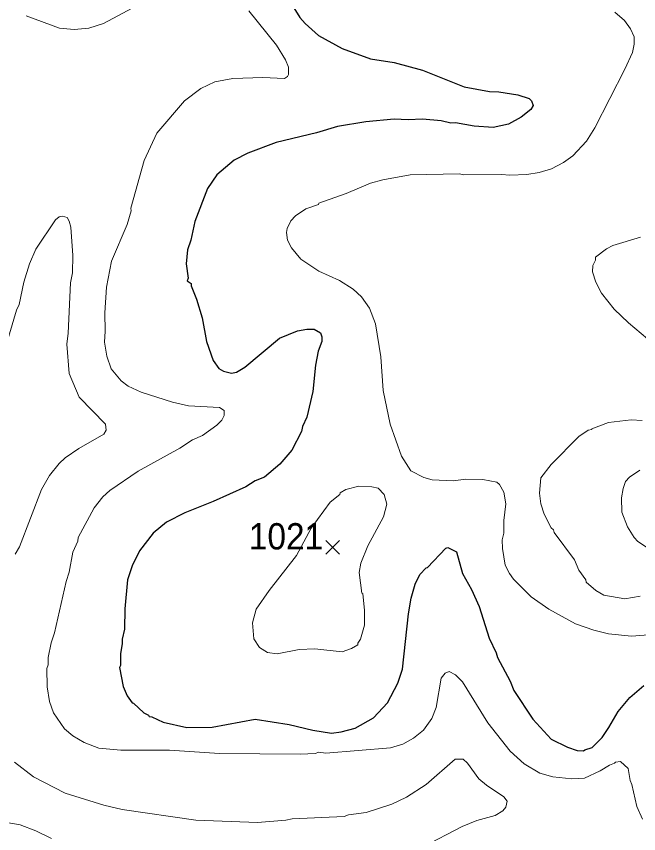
# Model space of a CAD drawing. Extents: x 265.7 to 292.1, y 7676.2 to 7704.2.
# Drawn here: x 284.034 to 285.928, y 7695.33 to 7697.815 of the extents above; entities that cross this region are included whole.
import ezdxf
from ezdxf.enums import TextEntityAlignment as Align

# ---------------------------------------------------------------- set-up
doc = ezdxf.new("R2010")
doc.units = 0
doc.header["$LTSCALE"] = 0.032
for name, color, linetype, lineweight in [('1', 7, 'Continuous', 25), ('2', 7, 'Continuous', 13), ('21', 7, 'Continuous', 25)]:
    doc.layers.add(name, color=color, linetype=linetype, lineweight=lineweight)
doc.layers.add('61', color=7, linetype='Continuous')

msp = doc.modelspace()

# ---------------------------------------------------------------- linework, layer by layer
at = {"layer": '1'}
for points in [[(284.8787, 7697.8409), (284.8971, 7697.8114), (284.913, 7697.7931), (284.9537, 7697.7563), (285.0256, 7697.7172), (285.1117, 7697.6861), (285.1836, 7697.675), (285.2697, 7697.651), (285.3974, 7697.6007), (285.474, 7697.5864), (285.5027, 7697.5856), (285.5602, 7697.5768), (285.5945, 7697.5656), (285.6017, 7697.5577), (285.6073, 7697.5441), (285.6001, 7697.5321), (285.5705, 7697.5082), (285.5315, 7697.4874), (285.4852, 7697.4771), (285.4277, 7697.4811), (285.3703, 7697.4914), (285.3559, 7697.4906), (285.3272, 7697.497), (285.2697, 7697.5026), (285.2266, 7697.5002), (285.1836, 7697.5026), (285.0974, 7697.4946), (285.0112, 7697.4803), (284.9474, 7697.4603), (284.8245, 7697.4316), (284.7383, 7697.3989), (284.6968, 7697.3773), (284.6441, 7697.3334), (284.6162, 7697.2919), (284.5779, 7697.1914), (284.5651, 7697.134), (284.5555, 7697.1052), (284.5516, 7697.0621), (284.5571, 7697.019), (284.5547, 7697.0103), (284.5659, 7697.0023), (284.5659, 7696.9951), (284.5827, 7696.9552), (284.5994, 7696.8978), (284.613, 7696.8259), (284.6329, 7696.7685), (284.6505, 7696.7437), (284.6649, 7696.7365), (284.6888, 7696.7302), (284.7048, 7696.7334), (284.7295, 7696.7485), (284.8348, 7696.8363), (284.8899, 7696.8586), (284.9186, 7696.8642), (284.9402, 7696.8642), (284.9601, 7696.8523), (284.9641, 7696.8403), (284.9641, 7696.8259), (284.9529, 7696.7972), (284.9442, 7696.7541), (284.937, 7696.6743), (284.9178, 7696.5961), (284.905, 7696.5674), (284.9019, 7696.553), (284.8723, 7696.4956), (284.8364, 7696.4533), (284.7894, 7696.4142), (284.7606, 7696.4022), (284.7327, 7696.3847), (284.633, 7696.34), (284.5468, 7696.3057), (284.4917, 7696.2769)], [(284.4917, 7696.2769), (284.451, 7696.2434), (284.4095, 7696.19), (284.3864, 7696.1445), (284.3728, 7696.1014), (284.3648, 7696.0136), (284.3632, 7695.9514)], [(284.3632, 7695.9514), (284.3561, 7695.921), (284.3569, 7695.9067), (284.3513, 7695.878), (284.3513, 7695.8412), (284.3481, 7695.8349), (284.3592, 7695.7774), (284.372, 7695.7487), (284.3864, 7695.7271), (284.3912, 7695.7263), (284.4223, 7695.6976), (284.4367, 7695.6904), (284.4391, 7695.6856), (284.447, 7695.6848), (284.4813, 7695.6689), (284.5532, 7695.6521), (284.6298, 7695.6537), (284.7606, 7695.6777), (284.8644, 7695.6617), (284.9362, 7695.6441), (284.9936, 7695.6354), (285.0224, 7695.6394), (285.0655, 7695.6505), (285.1213, 7695.6824), (285.1636, 7695.7279), (285.1955, 7695.787), (285.2091, 7695.8301), (285.2274, 7695.9977), (285.2362, 7696.0455), (285.2482, 7696.0886), (285.2625, 7696.1173), (285.2809, 7696.1381), (285.2857, 7696.1389), (285.3415, 7696.1979), (285.3471, 7696.2003), (285.3735, 7696.1868), (285.3918, 7696.1205), (285.4197, 7696.0719), (285.4429, 7696.02), (285.4732, 7695.9242), (285.4947, 7695.8796), (285.4987, 7695.8652), (285.537, 7695.7934), (285.5482, 7695.7646), (285.6057, 7695.6777), (285.6615, 7695.617), (285.7118, 7695.5923), (285.7405, 7695.5827), (285.7605, 7695.5811), (285.7637, 7695.5851), (285.7868, 7695.5915), (285.8163, 7695.6226), (285.8371, 7695.6521), (285.865, 7695.7008), (285.9009, 7695.7439), (285.944, 7695.7806)]]:
    msp.add_lwpolyline(points, dxfattribs=at)
at = {"layer": '2'}
for points in [[(284.3872, 7697.8401), (284.2994, 7697.7931), (284.2547, 7697.7795), (284.21, 7697.7755), (284.1654, 7697.7795), (284.0648, 7697.8162)], [(284.8628, 7697.6383), (284.8628, 7697.6606), (284.8532, 7697.6829), (284.8261, 7697.7276), (284.7415, 7697.8322)], [(285.0846, 7696.9616), (285.0591, 7696.9855), (285.0176, 7697.0119), (284.9553, 7697.0406), (284.9003, 7697.0765), (284.8715, 7697.1116), (284.8596, 7697.134), (284.8564, 7697.1579), (284.858, 7697.1699), (284.8699, 7697.193), (284.8843, 7697.2082), (284.9154, 7697.2297), (284.9537, 7697.2425), (284.9545, 7697.2465), (285.0383, 7697.2768), (285.1117, 7697.3079), (285.15, 7697.3183), (285.233, 7697.3326), (285.383, 7697.3358), (285.3958, 7697.3326), (285.5107, 7697.3342), (285.5363, 7697.3318), (285.5873, 7697.3342), (285.6256, 7697.3406), (285.6623, 7697.3518), (285.699, 7697.3701), (285.7278, 7697.3909), (285.7693, 7697.4356), (285.7948, 7697.4755), (285.8858, 7697.6542), (285.9089, 7697.7053), (285.9145, 7697.7308), (285.9137, 7697.7532), (285.9033, 7697.7771), (285.885, 7697.8026), (285.8554, 7697.8274)], [(284.5962, 7697.5952), (284.6385, 7697.6159), (284.6936, 7697.6263), (284.7846, 7697.6287), (284.85, 7697.6263), (284.8596, 7697.6319), (284.8628, 7697.6383)], [(285.94, 7695.3736), (285.9225, 7695.412), (285.9073, 7695.479), (285.9017, 7695.4909), (285.8961, 7695.5277), (285.873, 7695.5492), (285.857, 7695.5476), (285.8546, 7695.5436), (285.8395, 7695.538), (285.8108, 7695.5205), (285.7629, 7695.4989), (285.7246, 7695.4965), (285.6671, 7695.5029), (285.6272, 7695.5141), (285.5793, 7695.542), (285.537, 7695.5803), (285.4692, 7695.6665), (285.3918, 7695.7918), (285.3703, 7695.8125), (285.3511, 7695.8229), (285.3391, 7695.8173), (285.3272, 7695.8022), (285.312, 7695.7136), (285.2985, 7695.6801), (285.2729, 7695.6441), (285.2426, 7695.6202), (285.2107, 7695.6019), (285.1724, 7695.5907), (284.9761, 7695.5747), (284.9537, 7695.5779), (284.945, 7695.5739), (284.8979, 7695.5715), (284.6521, 7695.5739), (284.5005, 7695.5835), (284.3521, 7695.5835), (284.285, 7695.5899), (284.2404, 7695.6066), (284.206, 7695.6274), (284.1813, 7695.6481), (284.1478, 7695.6976), (284.135, 7695.7311), (284.1286, 7695.7758), (284.127, 7695.8317), (284.1318, 7695.8428), (284.1318, 7695.8652), (284.1406, 7695.9099), (284.151, 7695.9402), (284.1861, 7696.0966), (284.1957, 7696.1253), (284.2068, 7696.186), (284.2212, 7696.2195), (284.2228, 7696.2307), (284.2715, 7696.32), (284.2978, 7696.3535), (284.3194, 7696.3727), (284.4055, 7696.4317), (284.5316, 7696.502), (284.5707, 7696.5275), (284.601, 7696.5403), (284.6441, 7696.5722), (284.6593, 7696.5873), (284.6665, 7696.6009), (284.6665, 7696.6169), (284.6521, 7696.6256), (284.558, 7696.6304), (284.5101, 7696.6416), (284.4143, 7696.6719), (284.3744, 7696.6903), (284.3537, 7696.707), (284.3225, 7696.7429), (284.3098, 7696.7813), (284.3026, 7696.8243), (284.305, 7696.8579), (284.3034, 7696.9137), (284.309, 7696.9919), (284.3241, 7697.0701), (284.3712, 7697.1818), (284.384, 7697.2233), (284.3832, 7697.2321), (284.4239, 7697.3765), (284.4622, 7697.4595), (284.546, 7697.5577), (284.5962, 7697.5952)], [(284.001, 7696.8052), (284.0345, 7696.9217), (284.0433, 7696.9392), (284.0568, 7697.0063), (284.0744, 7697.0621), (284.0935, 7697.1068), (284.1534, 7697.1962), (284.1645, 7697.2058), (284.1749, 7697.2074), (284.1893, 7697.2034), (284.1957, 7697.1922), (284.2005, 7697.1738), (284.206, 7697.0877), (284.2052, 7697.035), (284.1997, 7697.0047), (284.1925, 7696.8515), (284.1877, 7696.818), (284.1957, 7696.7286), (284.226, 7696.6568), (284.3058, 7696.5746), (284.3074, 7696.5562), (284.301, 7696.5443), (284.2244, 7696.5012), (284.1829, 7696.4724), (284.1646, 7696.4549), (284.1358, 7696.419), (284.1111, 7696.3759), (284.0441, 7696.2019), (284.0305, 7696.1796)], [(285.9336, 7697.1435), (285.8491, 7697.118), (285.8299, 7697.1084), (285.7964, 7697.0829), (285.7964, 7697.0741), (285.7884, 7697.0573), (285.7876, 7697.0382), (285.7972, 7697.0063), (285.8147, 7696.9736), (285.8538, 7696.9249), (285.8969, 7696.8826), (285.9552, 7696.8339)], [(285.2067, 7696.478), (285.1716, 7696.5754), (285.1508, 7696.6775), (285.1436, 7696.7797), (285.1269, 7696.8802), (285.1085, 7696.9281), (285.0846, 7696.9616)], [(285.9328, 7696.0519), (285.8858, 7696.0439), (285.8219, 7696.0551), (285.798, 7696.0695), (285.7685, 7696.0942), (285.7669, 7696.1014), (285.7453, 7696.1309), (285.7325, 7696.162), (285.6703, 7696.245), (285.6687, 7696.2538), (285.6615, 7696.2594), (285.64, 7696.3009), (285.6304, 7696.3328), (285.6264, 7696.3647), (285.6304, 7696.4118), (285.6615, 7696.4525), (285.7453, 7696.5371), (285.774, 7696.5562), (285.7852, 7696.5586), (285.7852, 7696.561), (285.8363, 7696.5802), (285.9049, 7696.5881), (285.9384, 7696.5857)], [(285.9831, 7695.9362), (285.9065, 7695.9306), (285.8363, 7695.9378), (285.7916, 7695.949), (285.7357, 7695.9681), (285.6543, 7696.012), (285.6009, 7696.0495), (285.5474, 7696.1038), (285.5346, 7696.1205), (285.5219, 7696.1461), (285.5131, 7696.1971), (285.5123, 7696.2227), (285.5179, 7696.2434), (285.5179, 7696.2817), (285.5235, 7696.3328), (285.5179, 7696.3679), (285.5043, 7696.3918), (285.4963, 7696.3982), (285.4533, 7696.407), (285.4022, 7696.4078), (285.3639, 7696.403), (285.3001, 7696.4054), (285.2745, 7696.4126), (285.2346, 7696.4333), (285.2067, 7696.478)], [(285.9312, 7696.4349), (285.9001, 7696.4134), (285.8881, 7696.4006), (285.8802, 7696.3791), (285.8754, 7696.3504), (285.877, 7696.3073), (285.8937, 7696.2626), (285.9137, 7696.2299), (285.9256, 7696.2179), (285.9703, 7696.1892)], [(284.0289, 7695.5476), (284.0872, 7695.5021), (284.1829, 7695.4526), (284.301, 7695.4159), (284.3569, 7695.4032), (284.5803, 7695.3712), (284.7686, 7695.3641), (284.8548, 7695.3704), (284.8739, 7695.3744), (285.0319, 7695.3824), (285.0455, 7695.3872), (285.099, 7695.3944), (285.1772, 7695.4191), (285.2219, 7695.4407), (285.2809, 7695.479), (285.3695, 7695.5564), (285.3934, 7695.5564), (285.407, 7695.5444), (285.4413, 7695.4965), (285.4644, 7695.4774), (285.5179, 7695.4415), (285.5275, 7695.4287), (285.5235, 7695.4104), (285.5147, 7695.3992), (285.4916, 7695.3848), (285.4357, 7695.3697), (285.391, 7695.3513), (285.2697, 7695.2891)], [(284.0058, 7695.3633), (284.0457, 7695.3569), (284.0935, 7695.3385), (284.1414, 7695.3154)]]:
    msp.add_lwpolyline(points, dxfattribs=at)
msp.add_lwpolyline([(284.9315, 7696.2591), (284.8867, 7696.1756), (284.8037, 7696.0695), (284.7638, 7696.0128), (284.7534, 7695.9705), (284.7566, 7695.9226), (284.7742, 7695.8955), (284.7989, 7695.8803), (284.8277, 7695.8764), (284.8947, 7695.8899), (284.9426, 7695.8915), (285.0256, 7695.8827), (285.0543, 7695.8923), (285.0734, 7695.9043), (285.0734, 7695.9091), (285.0814, 7695.921), (285.0934, 7695.9641), (285.0934, 7696.0088), (285.0886, 7696.0599), (285.0854, 7696.0615), (285.0774, 7696.1237), (285.0822, 7696.1525), (285.1037, 7696.2051), (285.1516, 7696.2929), (285.162, 7696.3312), (285.154, 7696.3607), (285.1349, 7696.3799), (285.1165, 7696.3847), (285.0766, 7696.3863), (285.0367, 7696.3759), (285.02, 7696.3663), (285.0184, 7696.3615), (284.9896, 7696.3376)], close=True, dxfattribs=at)
at = {"layer": '21'}
for p, q in [((284.9761, 7696.2211), (285.0173, 7696.1799)), ((285.0173, 7696.2211), (284.9761, 7696.1799))]:
    msp.add_line(p, q, dxfattribs=at)

# ---------------------------------------------------------------- texts
at = {"layer": '61', "width": 0.95}
msp.add_text('1021', height=0.08, dxfattribs=at).set_placement((284.8549, 7696.1939), align=Align.CENTER)

doc.saveas('drawing.dxf')
